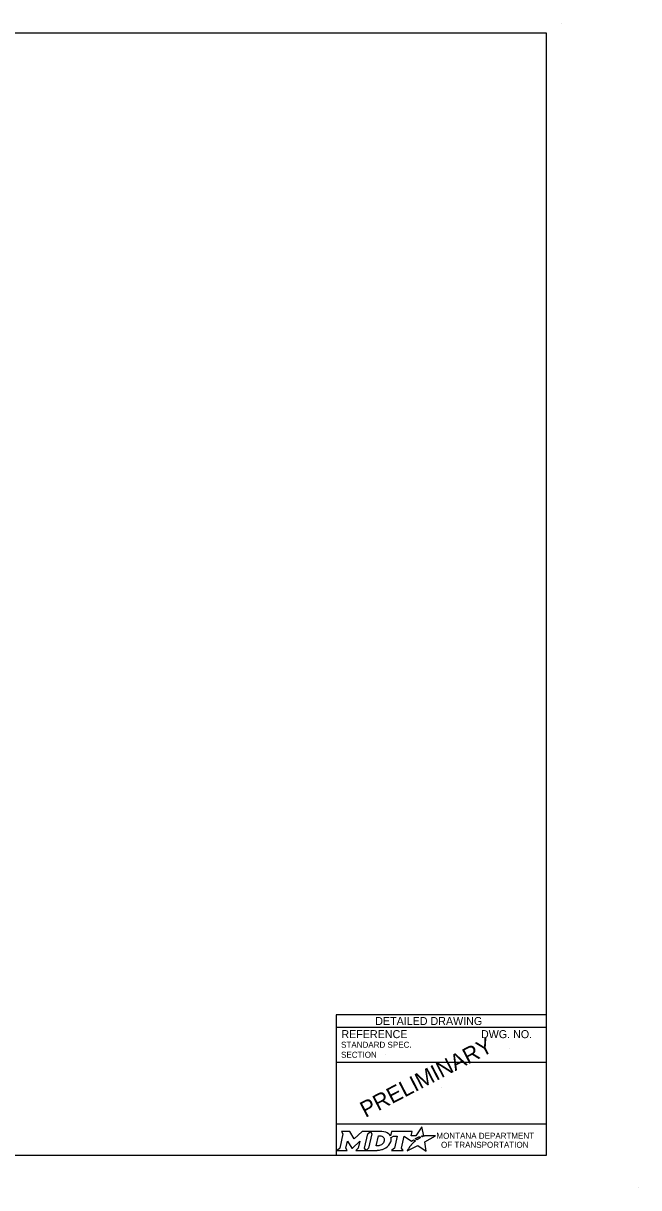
# Model space of a CAD drawing. Extents: x 49991.4 to 50041.6, y 49987.6 to 50011.4.
# Drawn here: x 50003.39 to 50009.54, y 49999.74 to 50011.36 of the extents above; entities that cross this region are included whole.
import ezdxf

# ---------------------------------------------------------------- set-up
doc = ezdxf.new("R2010")
doc.units = 0
doc.layers.add('Level 1', color=7, linetype='Continuous')
doc.layers.add('Level 2', color=7, linetype='Continuous')

msp = doc.modelspace()

# ---------------------------------------------------------------- linework, layer by layer
at = {"layer": 'Level 1'}
for p, q in [((50008.765, 50011.363), (50008.765, 50011.363)), ((50009.537, 49999.736), (50009.537, 49999.736))]:
    msp.add_line(p, q, dxfattribs=at)
msp.add_lwpolyline([(50008.615, 50011.263), (50000.336, 50011.263), (50000.336, 50000.062), (50008.615, 50000.062)], close=True, dxfattribs=at)
at = {"layer": 'Level 2'}
for p, q in [((50008.615, 50001.462), (50006.515, 50001.462)), ((50006.515, 50001.462), (50006.515, 50000.062)), ((50008.615, 50001.337), (50006.515, 50001.337)), ((50007.009, 50001.063), (50007.009, 50001.063)), ((50008.251, 50001.122), (50008.251, 50001.122)), ((50008.615, 50000.987), (50006.515, 50000.987)), ((50007.565, 50000.738), (50007.565, 50000.738)), ((50008.615, 50000.369), (50006.515, 50000.369))]:
    msp.add_line(p, q, dxfattribs=at)
for points in [[(50007.377, 50000.245), (50007.367, 50000.25), (50007.378, 50000.253), (50007.39, 50000.255), (50007.373, 50000.345), (50007.313, 50000.254), (50007.266, 50000.253), (50007.276, 50000.297), (50007.067, 50000.297), (50007.057, 50000.255), (50007.051, 50000.263)], [(50006.57, 50000.297), (50006.584, 50000.274), (50006.551, 50000.131), (50006.525, 50000.108), (50006.627, 50000.108), (50006.613, 50000.131), (50006.629, 50000.201), (50006.673, 50000.132), (50006.678, 50000.132), (50006.753, 50000.202), (50006.737, 50000.13), (50006.712, 50000.108), (50006.814, 50000.108), (50006.8, 50000.132), (50006.833, 50000.274)], [(50006.833, 50000.274), (50006.859, 50000.297), (50006.776, 50000.297), (50006.697, 50000.224), (50006.652, 50000.297), (50006.57, 50000.297)], [(50006.972, 50000.297), (50006.859, 50000.297), (50006.873, 50000.275), (50006.839, 50000.131), (50006.814, 50000.108), (50006.925, 50000.108)], [(50006.996, 50000.211), (50006.995, 50000.203), (50006.992, 50000.193), (50006.988, 50000.185), (50006.982, 50000.178), (50006.976, 50000.171), (50006.968, 50000.164), (50006.959, 50000.16), (50006.95, 50000.156), (50006.941, 50000.154), (50006.932, 50000.153), (50006.916, 50000.153), (50006.94, 50000.253), (50006.956, 50000.253), (50006.963, 50000.252), (50006.971, 50000.25), (50006.977, 50000.247), (50006.983, 50000.243), (50006.988, 50000.238), (50006.992, 50000.232), (50006.995, 50000.226), (50006.996, 50000.218), (50006.996, 50000.215), (50006.996, 50000.211)], [(50007.064, 50000.238), (50007.088, 50000.251), (50007.125, 50000.251), (50007.097, 50000.131), (50007.069, 50000.108), (50007.185, 50000.108), (50007.168, 50000.131), (50007.196, 50000.251), (50007.268, 50000.2), (50007.289, 50000.215), (50007.309, 50000.204)], [(50007.253, 50000.148), (50007.237, 50000.124), (50007.233, 50000.116), (50007.227, 50000.107), (50007.225, 50000.103), (50007.33, 50000.156), (50007.414, 50000.101), (50007.401, 50000.194), (50007.508, 50000.252), (50007.458, 50000.253), (50007.428, 50000.253), (50007.407, 50000.254), (50007.401, 50000.252), (50007.396, 50000.251), (50007.387, 50000.249), (50007.377, 50000.245)], [(50007.327, 50000.217), (50007.324, 50000.215), (50007.306, 50000.225), (50007.316, 50000.231), (50007.32, 50000.233), (50007.329, 50000.237), (50007.335, 50000.239), (50007.343, 50000.243), (50007.35, 50000.245), (50007.362, 50000.238), (50007.358, 50000.236), (50007.353, 50000.233), (50007.349, 50000.231), (50007.344, 50000.228), (50007.342, 50000.227), (50007.339, 50000.225), (50007.337, 50000.224), (50007.334, 50000.222), (50007.332, 50000.221), (50007.329, 50000.219), (50007.327, 50000.217)], [(50006.97, 50000.116), (50006.979, 50000.118), (50006.992, 50000.124), (50007.012, 50000.135)], [(50007.267, 50000.164), (50007.267, 50000.164)]]:
    msp.add_lwpolyline(points, dxfattribs=at)
for centre, radius, start, end in [((50006.995, 50000.219), 0.0709, 339.5329, 15.8582), ((50006.951, 50000.236), 0.118, 300.9103, 339.1383)]:
    msp.add_arc(centre, radius, start, end, dxfattribs=at)
for centre, major_axis, ratio, start_param, end_param in [((50006.97, 50000.25), (0.0834, -0.0037), 0.568097, 0.61298, 1.570796), ((50007.026, 50000.257), (0.0361, -0.0295), 0.469099, 1.225588, 1.570796), ((50006.925, 50000.257), (0, 0.148), 0.987302, 3.139398, 3.456847), ((50007.26, 50000.156), (-0.00694, -0.00806), 0.008222, 0, 3.137361), ((50007.276, 50000.174), (-0.0098, -0.0102), 0.016458, 3.141593, 6.279097), ((50007.297, 50000.194), (-0.0112, -0.0097), 0.021651, 3.157348, 6.283185)]:
    msp.add_ellipse(centre, major_axis=major_axis, ratio=ratio, start_param=start_param, end_param=end_param, dxfattribs=at)

# ---------------------------------------------------------------- texts
for s, height, p in [('DETAILED DRAWING', 0.0799, (50006.906, 50001.36)), ('REFERENCE', 0.08, (50006.568, 50001.229)), ('DWG. NO.', 0.08, (50007.962, 50001.229)), ('STANDARD SPEC.', 0.06, (50006.565, 50001.133)), ('SECTION', 0.06, (50006.565, 50001.033))]:
    msp.add_text(s, height=height, dxfattribs=at).set_placement(p)
for s, height, rotation, p in [('PRELIMINARY', 0.16, 27.5, (50006.808, 50000.432)), ('MONTANA DEPARTMENT', 0.06, 360, (50007.517, 50000.224)), ('OF TRANSPORTATION', 0.06, 360, (50007.563, 50000.134))]:
    msp.add_text(s, height=height, rotation=rotation, dxfattribs=at).set_placement(p)

doc.saveas('drawing.dxf')
